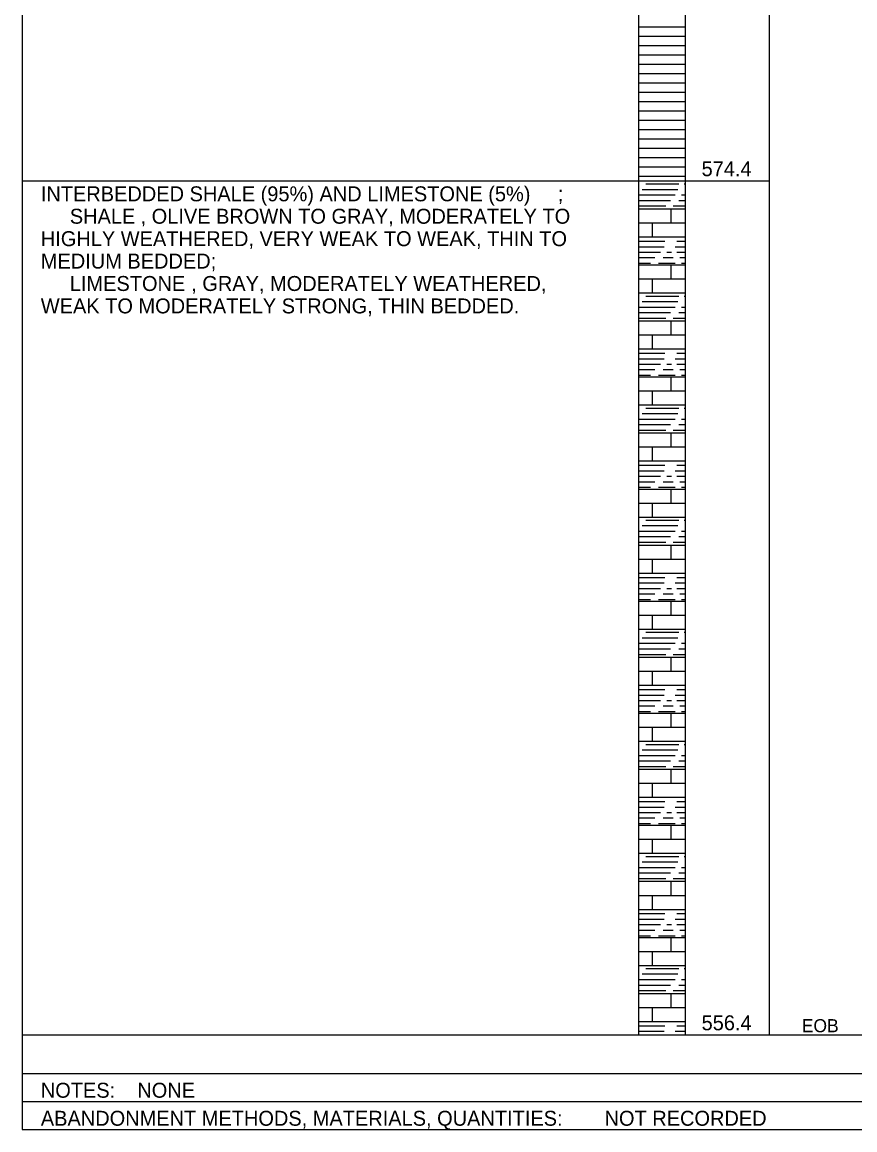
# Model space of a CAD drawing. Extents: x 0 to 0.833, y -0.381 to 0.608.
# Drawn here: x 0 to 0.3715, y -0.381 to 0.1131 of the extents above; entities that cross this region are included whole.
import ezdxf

# ---------------------------------------------------------------- set-up
doc = ezdxf.new("R2010")
doc.units = 0

msp = doc.modelspace()

# ---------------------------------------------------------------- linework, layer by layer
msp.add_lwpolyline([(0, -0.38086), (0.83333, -0.38086), (0.83333, 0.60833), (0, 0.60833)], close=True)
for points in [[(0.29583, 0.55417), (0.29583, -0.33867)], [(0.29583, 0.55417), (0.29583, -0.33867)], [(0.33333, 0.55417), (0.33333, -0.33867)], [(0.33333, 0.55417), (0.33333, -0.33867)], [(0.275, 0.52917), (0.275, -0.33867)], [(0.275, 0.16933), (0.275, 0.04233)], [(0.275, 0.111), (0.29583, 0.111)], [(0.275, 0.10683), (0.29583, 0.10683)], [(0.275, 0.10267), (0.29583, 0.10267)], [(0.275, 0.0985), (0.29583, 0.0985)], [(0.275, 0.09433), (0.29583, 0.09433)], [(0.275, 0.09017), (0.29583, 0.09017)], [(0.275, 0.086), (0.29583, 0.086)], [(0.275, 0.08183), (0.29583, 0.08183)], [(0.275, 0.07767), (0.29583, 0.07767)], [(0.275, 0.0735), (0.29583, 0.0735)], [(0.275, 0.06933), (0.29583, 0.06933)], [(0.275, 0.06517), (0.29583, 0.06517)], [(0.275, 0.061), (0.29583, 0.061)], [(0.275, 0.05683), (0.29583, 0.05683)], [(0.275, 0.05267), (0.29583, 0.05267)], [(0.275, 0.0485), (0.29583, 0.0485)], [(0, 0.04233), (0.275, 0.04233)], [(0.275, 0.04433), (0.29583, 0.04433)], [(0.275, 0.04233), (0.29583, 0.04233)], [(0.275, 0.04233), (0.29583, 0.04233)], [(0.275, 0.04233), (0.275, -0.33867)], [(0.27825, 0.04092), (0.293, 0.04092)], [(0.29542, 0.04092), (0.29583, 0.04092)], [(0.29583, 0.04233), (0.33333, 0.04233)], [(0.275, 0.036), (0.29133, 0.036)], [(0.27667, 0.0385), (0.29258, 0.0385)], [(0.29417, 0.036), (0.29583, 0.036)], [(0.275, 0.03358), (0.28933, 0.03358)], [(0.275, 0.03108), (0.28725, 0.03108)], [(0.275, 0.02983), (0.29583, 0.02983)], [(0.28958, 0.02358), (0.28958, 0.02983)], [(0.2905, 0.03108), (0.29583, 0.03108)], [(0.293, 0.03358), (0.29583, 0.03358)], [(0.275, 0.02358), (0.29583, 0.02358)], [(0.28125, 0.01733), (0.28125, 0.02358)], [(0.275, 0.01733), (0.29583, 0.01733)], [(0.275, 0.01542), (0.28683, 0.01542)], [(0.29217, 0.01542), (0.29583, 0.01542)], [(0.275, 0.01292), (0.28642, 0.01292)], [(0.275, 0.0105), (0.28483, 0.0105)], [(0.28767, 0.0105), (0.28967, 0.0105)], [(0.29133, 0.01292), (0.29583, 0.01292)], [(0.29217, 0.0105), (0.29583, 0.0105)], [(0.275, 0.00808), (0.28233, 0.00808)], [(0.275, 0.00558), (0.28033, 0.00558)], [(0.284, 0.00558), (0.29133, 0.00558)], [(0.286, 0.00808), (0.2905, 0.00808)], [(0.29342, 0.00808), (0.29583, 0.00808)], [(0.29417, 0.00558), (0.29583, 0.00558)], [(0.275, 0.00483), (0.29583, 0.00483)], [(0.28958, -0.00142), (0.28958, 0.00483)], [(0.275, -0.00142), (0.29583, -0.00142)], [(0.28125, -0.00767), (0.28125, -0.00142)], [(0.275, -0.00767), (0.29583, -0.00767)], [(0.27825, -0.00908), (0.293, -0.00908)], [(0.29542, -0.00908), (0.29583, -0.00908)], [(0.275, -0.014), (0.29133, -0.014)], [(0.27667, -0.0115), (0.29258, -0.0115)], [(0.29417, -0.014), (0.29583, -0.014)], [(0.275, -0.01642), (0.28933, -0.01642)], [(0.275, -0.01892), (0.28725, -0.01892)], [(0.2905, -0.01892), (0.29583, -0.01892)], [(0.293, -0.01642), (0.29583, -0.01642)], [(0.275, -0.02017), (0.29583, -0.02017)], [(0.28958, -0.02642), (0.28958, -0.02017)], [(0.275, -0.02642), (0.29583, -0.02642)], [(0.28125, -0.03267), (0.28125, -0.02642)], [(0.275, -0.03267), (0.29583, -0.03267)], [(0.275, -0.03458), (0.28683, -0.03458)], [(0.29217, -0.03458), (0.29583, -0.03458)], [(0.275, -0.03708), (0.28642, -0.03708)], [(0.275, -0.0395), (0.28483, -0.0395)], [(0.28767, -0.0395), (0.28967, -0.0395)], [(0.29133, -0.03708), (0.29583, -0.03708)], [(0.29217, -0.0395), (0.29583, -0.0395)], [(0.275, -0.04192), (0.28233, -0.04192)], [(0.275, -0.04442), (0.28033, -0.04442)], [(0.284, -0.04442), (0.29133, -0.04442)], [(0.286, -0.04192), (0.2905, -0.04192)], [(0.29342, -0.04192), (0.29583, -0.04192)], [(0.29417, -0.04442), (0.29583, -0.04442)], [(0.275, -0.04517), (0.29583, -0.04517)], [(0.28958, -0.05142), (0.28958, -0.04517)], [(0.275, -0.05142), (0.29583, -0.05142)], [(0.28125, -0.05767), (0.28125, -0.05142)], [(0.275, -0.05767), (0.29583, -0.05767)], [(0.27825, -0.05908), (0.293, -0.05908)], [(0.29542, -0.05908), (0.29583, -0.05908)], [(0.275, -0.064), (0.29133, -0.064)], [(0.27667, -0.0615), (0.29258, -0.0615)], [(0.29417, -0.064), (0.29583, -0.064)], [(0.275, -0.06642), (0.28933, -0.06642)], [(0.275, -0.06892), (0.28725, -0.06892)], [(0.2905, -0.06892), (0.29583, -0.06892)], [(0.293, -0.06642), (0.29583, -0.06642)], [(0.275, -0.07017), (0.29583, -0.07017)], [(0.28958, -0.07642), (0.28958, -0.07017)], [(0.275, -0.07642), (0.29583, -0.07642)], [(0.28125, -0.08267), (0.28125, -0.07642)], [(0.275, -0.08267), (0.29583, -0.08267)], [(0.275, -0.08458), (0.28683, -0.08458)], [(0.275, -0.08708), (0.28642, -0.08708)], [(0.29133, -0.08708), (0.29583, -0.08708)], [(0.29217, -0.08458), (0.29583, -0.08458)], [(0.275, -0.0895), (0.28483, -0.0895)], [(0.275, -0.09192), (0.28233, -0.09192)], [(0.286, -0.09192), (0.2905, -0.09192)], [(0.28767, -0.0895), (0.28967, -0.0895)], [(0.29217, -0.0895), (0.29583, -0.0895)], [(0.29342, -0.09192), (0.29583, -0.09192)], [(0.275, -0.09442), (0.28033, -0.09442)], [(0.275, -0.09517), (0.29583, -0.09517)], [(0.284, -0.09442), (0.29133, -0.09442)], [(0.28958, -0.10142), (0.28958, -0.09517)], [(0.29417, -0.09442), (0.29583, -0.09442)], [(0.275, -0.10142), (0.29583, -0.10142)], [(0.28125, -0.10767), (0.28125, -0.10142)], [(0.275, -0.10767), (0.29583, -0.10767)], [(0.27667, -0.1115), (0.29258, -0.1115)], [(0.27825, -0.10908), (0.293, -0.10908)], [(0.29542, -0.10908), (0.29583, -0.10908)], [(0.275, -0.114), (0.29133, -0.114)], [(0.275, -0.11642), (0.28933, -0.11642)], [(0.293, -0.11642), (0.29583, -0.11642)], [(0.29417, -0.114), (0.29583, -0.114)], [(0.275, -0.11892), (0.28725, -0.11892)], [(0.275, -0.12017), (0.29583, -0.12017)], [(0.28958, -0.12642), (0.28958, -0.12017)], [(0.2905, -0.11892), (0.29583, -0.11892)], [(0.275, -0.12642), (0.29583, -0.12642)], [(0.28125, -0.13267), (0.28125, -0.12642)], [(0.275, -0.13267), (0.29583, -0.13267)], [(0.275, -0.13458), (0.28683, -0.13458)], [(0.275, -0.13708), (0.28642, -0.13708)], [(0.29133, -0.13708), (0.29583, -0.13708)], [(0.29217, -0.13458), (0.29583, -0.13458)], [(0.275, -0.1395), (0.28483, -0.1395)], [(0.275, -0.14192), (0.28233, -0.14192)], [(0.286, -0.14192), (0.2905, -0.14192)], [(0.28767, -0.1395), (0.28967, -0.1395)], [(0.29217, -0.1395), (0.29583, -0.1395)], [(0.29342, -0.14192), (0.29583, -0.14192)], [(0.275, -0.14442), (0.28033, -0.14442)], [(0.275, -0.14517), (0.29583, -0.14517)], [(0.284, -0.14442), (0.29133, -0.14442)], [(0.28958, -0.15142), (0.28958, -0.14517)], [(0.29417, -0.14442), (0.29583, -0.14442)], [(0.275, -0.15142), (0.29583, -0.15142)], [(0.28125, -0.15767), (0.28125, -0.15142)], [(0.275, -0.15767), (0.29583, -0.15767)], [(0.27667, -0.1615), (0.29258, -0.1615)], [(0.27825, -0.15908), (0.293, -0.15908)], [(0.29542, -0.15908), (0.29583, -0.15908)], [(0.275, -0.164), (0.29133, -0.164)], [(0.275, -0.16642), (0.28933, -0.16642)], [(0.293, -0.16642), (0.29583, -0.16642)], [(0.29417, -0.164), (0.29583, -0.164)], [(0.275, -0.16892), (0.28725, -0.16892)], [(0.275, -0.17017), (0.29583, -0.17017)], [(0.28958, -0.17642), (0.28958, -0.17017)], [(0.2905, -0.16892), (0.29583, -0.16892)], [(0.275, -0.17642), (0.29583, -0.17642)], [(0.28125, -0.18267), (0.28125, -0.17642)], [(0.275, -0.18267), (0.29583, -0.18267)], [(0.275, -0.18458), (0.28683, -0.18458)], [(0.275, -0.18708), (0.28642, -0.18708)], [(0.29133, -0.18708), (0.29583, -0.18708)], [(0.29217, -0.18458), (0.29583, -0.18458)], [(0.275, -0.1895), (0.28483, -0.1895)], [(0.275, -0.19192), (0.28233, -0.19192)], [(0.286, -0.19192), (0.2905, -0.19192)], [(0.28767, -0.1895), (0.28967, -0.1895)], [(0.29217, -0.1895), (0.29583, -0.1895)], [(0.29342, -0.19192), (0.29583, -0.19192)], [(0.275, -0.19442), (0.28033, -0.19442)], [(0.275, -0.19517), (0.29583, -0.19517)], [(0.284, -0.19442), (0.29133, -0.19442)], [(0.28958, -0.20142), (0.28958, -0.19517)], [(0.29417, -0.19442), (0.29583, -0.19442)], [(0.275, -0.20142), (0.29583, -0.20142)], [(0.28125, -0.20767), (0.28125, -0.20142)], [(0.275, -0.20767), (0.29583, -0.20767)], [(0.27667, -0.2115), (0.29258, -0.2115)], [(0.27825, -0.20908), (0.293, -0.20908)], [(0.29542, -0.20908), (0.29583, -0.20908)], [(0.275, -0.214), (0.29133, -0.214)], [(0.275, -0.21642), (0.28933, -0.21642)], [(0.293, -0.21642), (0.29583, -0.21642)], [(0.29417, -0.214), (0.29583, -0.214)], [(0.275, -0.21892), (0.28725, -0.21892)], [(0.275, -0.22017), (0.29583, -0.22017)], [(0.28958, -0.22642), (0.28958, -0.22017)], [(0.2905, -0.21892), (0.29583, -0.21892)], [(0.275, -0.22642), (0.29583, -0.22642)], [(0.28125, -0.23267), (0.28125, -0.22642)], [(0.275, -0.23267), (0.29583, -0.23267)], [(0.275, -0.23458), (0.28683, -0.23458)], [(0.275, -0.23708), (0.28642, -0.23708)], [(0.29133, -0.23708), (0.29583, -0.23708)], [(0.29217, -0.23458), (0.29583, -0.23458)], [(0.275, -0.2395), (0.28483, -0.2395)], [(0.275, -0.24192), (0.28233, -0.24192)], [(0.286, -0.24192), (0.2905, -0.24192)], [(0.28767, -0.2395), (0.28967, -0.2395)], [(0.29217, -0.2395), (0.29583, -0.2395)], [(0.29342, -0.24192), (0.29583, -0.24192)], [(0.275, -0.24442), (0.28033, -0.24442)], [(0.275, -0.24517), (0.29583, -0.24517)], [(0.284, -0.24442), (0.29133, -0.24442)], [(0.28958, -0.25142), (0.28958, -0.24517)], [(0.29417, -0.24442), (0.29583, -0.24442)], [(0.275, -0.25142), (0.29583, -0.25142)], [(0.28125, -0.25767), (0.28125, -0.25142)], [(0.275, -0.25767), (0.29583, -0.25767)], [(0.27667, -0.2615), (0.29258, -0.2615)], [(0.27825, -0.25908), (0.293, -0.25908)], [(0.29542, -0.25908), (0.29583, -0.25908)], [(0.275, -0.264), (0.29133, -0.264)], [(0.275, -0.26642), (0.28933, -0.26642)], [(0.293, -0.26642), (0.29583, -0.26642)], [(0.29417, -0.264), (0.29583, -0.264)], [(0, -0.26836), (0, -0.38086), (0.83333, -0.38086), (0.83333, -0.26836)], [(0.275, -0.26892), (0.28725, -0.26892)], [(0.275, -0.27017), (0.29583, -0.27017)], [(0.28958, -0.27642), (0.28958, -0.27017)], [(0.2905, -0.26892), (0.29583, -0.26892)], [(0.275, -0.27642), (0.29583, -0.27642)], [(0.28125, -0.28267), (0.28125, -0.27642)], [(0.275, -0.28267), (0.29583, -0.28267)], [(0.275, -0.28458), (0.28683, -0.28458)], [(0.29217, -0.28458), (0.29583, -0.28458)], [(0.275, -0.28708), (0.28642, -0.28708)], [(0.275, -0.2895), (0.28483, -0.2895)], [(0.28767, -0.2895), (0.28967, -0.2895)], [(0.29133, -0.28708), (0.29583, -0.28708)], [(0.29217, -0.2895), (0.29583, -0.2895)], [(0.275, -0.29192), (0.28233, -0.29192)], [(0.275, -0.29442), (0.28033, -0.29442)], [(0.275, -0.29517), (0.29583, -0.29517)], [(0.284, -0.29442), (0.29133, -0.29442)], [(0.286, -0.29192), (0.2905, -0.29192)], [(0.28958, -0.30142), (0.28958, -0.29517)], [(0.29342, -0.29192), (0.29583, -0.29192)], [(0.29417, -0.29442), (0.29583, -0.29442)], [(0.275, -0.30142), (0.29583, -0.30142)], [(0.28125, -0.30767), (0.28125, -0.30142)], [(0.275, -0.30767), (0.29583, -0.30767)], [(0.27825, -0.30908), (0.293, -0.30908)], [(0.29542, -0.30908), (0.29583, -0.30908)], [(0.275, -0.314), (0.29133, -0.314)], [(0.27667, -0.3115), (0.29258, -0.3115)], [(0.29417, -0.314), (0.29583, -0.314)], [(0.275, -0.31642), (0.28933, -0.31642)], [(0.275, -0.31892), (0.28725, -0.31892)], [(0.275, -0.32017), (0.29583, -0.32017)], [(0.28958, -0.32642), (0.28958, -0.32017)], [(0.2905, -0.31892), (0.29583, -0.31892)], [(0.293, -0.31642), (0.29583, -0.31642)], [(0.275, -0.32642), (0.29583, -0.32642)], [(0.28125, -0.33267), (0.28125, -0.32642)], [(0.275, -0.33267), (0.29583, -0.33267)], [(0.275, -0.33458), (0.28683, -0.33458)], [(0.29217, -0.33458), (0.29583, -0.33458)], [(0, -0.33867), (0.275, -0.33867)], [(0.275, -0.33708), (0.28642, -0.33708)], [(0.275, -0.33867), (0.29583, -0.33867)], [(0.275, -0.33867), (0.29583, -0.33867)], [(0.29133, -0.33708), (0.29583, -0.33708)], [(0.29583, -0.33867), (0.33333, -0.33867)], [(0.33333, -0.33867), (0.37917, -0.33867)], [(0, -0.35586), (0.83333, -0.35586)], [(0, -0.36836), (0.83333, -0.36836)]]:
    msp.add_lwpolyline(points)

# ---------------------------------------------------------------- texts
for s, height, p in [('574.4', 0.006667, (0.30316, 0.04438)), ('INTERBEDDED SHALE (95%) AND LIMESTONE (5%)', 0.0066667, (0.00833, 0.03317)), (';', 0.00667, (0.23898, 0.03317)), ('SHALE', 0.006667, (0.02127, 0.02317)), (', OLIVE BROWN TO GRAY, MODERATELY TO', 0.0066667, (0.05284, 0.02317)), ('HIGHLY WEATHERED, VERY WEAK TO WEAK, THIN TO', 0.0066667, (0.00833, 0.01317)), ('MEDIUM BEDDED;', 0.0066667, (0.00833, 0.00317)), ('LIMESTONE', 0.006667, (0.02127, -0.00683)), (', GRAY, MODERATELY WEATHERED,', 0.0066667, (0.07544, -0.00683)), ('WEAK TO MODERATELY STRONG, THIN BEDDED.', 0.0066667, (0.00833, -0.01683)), ('556.4', 0.006667, (0.30316, -0.33662)), ('EOB', 0.005833, (0.34786, -0.33748)), ('NOTES:', 0.006667, (0.00833, -0.3667)), ('NONE', 0.006667, (0.05139, -0.3667)), ('ABANDONMENT METHODS, MATERIALS, QUANTITIES:', 0.0066667, (0.00833, -0.3792)), ('NOT RECORDED', 0.0066667, (0.25986, -0.3792))]:
    msp.add_text(s, height=height).set_placement(p)

doc.saveas('drawing.dxf')
